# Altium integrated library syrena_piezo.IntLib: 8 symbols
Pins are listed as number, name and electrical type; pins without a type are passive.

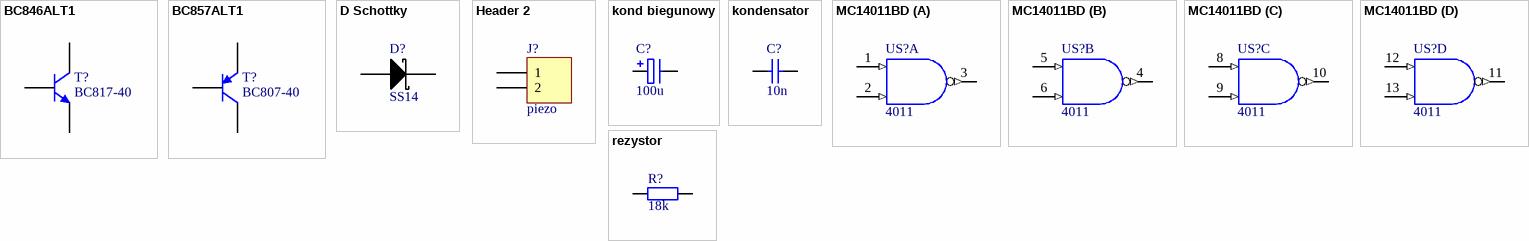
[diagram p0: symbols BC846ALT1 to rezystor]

## BC846ALT1
designator T?, comment BC817-40
General Purpose Transistor NPN Silicon
footprint 318-08 (SOT-23; 3 Leads; Body 3.0 x 2.6 mm, inc. leads (LxW max))
simulation model BC846ALT1 (NPN)
signal-integrity model BC846ALT1
pins: 1 B, 2 E, 3 C

## BC857ALT1
designator T?, comment BC807-40
General Purpose Transistor PNP Silicon
footprint 318-08 (SOT-23; 3 Leads; Body 3.0 x 2.6 mm, inc. leads (LxW max))
simulation model BC857ALT1 (PNP)
signal-integrity model BC857ALT1
pins: 1 B, 2 E, 3 C

## D Schottky
designator D?, comment SS14
Schottky Diode
footprint dioda 10mm
footprint dioda 17,5mm
footprint SMC/DO-214AB
footprint SMA/DO-214AC
pins: 1 A, 2 K

## Header 2
designator J?, comment piezo
Header, 2-Pin
footprint HDR1X2 (Connector; Header; 2 Position)
signal-integrity model Connector
pins: 1, 2

## kond biegunowy
designator C?, comment 100u
Polarized Capacitor
footprint Tantal B 3528-1411 (Capacitor, SM Tantalum; Body 3.5 x 2.8 mm (LxW typ))
footprint Tantal C 6032-2412 (Capacitor, SM Tantalum; Body 6.0 x 3.2 mm (LxW typ))
footprint Tantal D 7343-2917 (Capacitor, SM Tantalum; Body 7.3 x 4.3 mm (LxW typ))
footprint 2,5/5mm elektrolit
footprint 3,5/7mm elektrolit
footprint 5/10mm elektrolit
footprint 2,5/7mm elektrolit
footprint 7,5/16mm elektrolit
footprint 5/12,5mm elektrolit
footprint Tantal A 3216-1206 (Capacitor, SM Tantalum; Body 3.2 x 1.6 mm (LxW typ))
footprint A SMD elektrolit
footprint B SMD elektrolit
footprint C SMD elektrolit
footprint D SMD elektrolit
footprint E SMD elektrolit
footprint F SMD elektrolit
footprint 2,5/7mm le抗cy elektrolit
footprint 5/10mm le抗cy elektrolit
pins: 1, 2
1 alternate drawing of the same symbol

## kondensator
designator C?, comment 10n
footprint kond 2,5mm
footprint kond 7,5mm
footprint kond 10mm
footprint MELF-0805 (Metal Electrode Face (MELF) Resistor; Body 2 x 1.4 mm (LxDia))
footprint MELF-1206 (Metal Electrode Face (MELF) Resistor; Body 3.2 x 1.8 mm (LxDia))
footprint kond 15mm
footprint kond 5mm chudy
footprint kond 5mm gruby
footprint kond 5mm sredni
pins: 1, 2

## MC14011BD
designator US?, comment 4011
Quad 2-Input NAND Gate
footprint 751A-03_N (SOIC, 14-Leads, Body 8.7x3.9mm, Pitch 1.27mm, IPC Medium Density)
footprint 751A-03_L (SOIC, 14-Leads, Body 8.7x3.9mm, Pitch 1.27mm, IPC High Density)
footprint 751A-03_M (SOIC, 14-Leads, Body 8.7x3.9mm, Pitch 1.27mm, IPC Low Density)
pins on every part: 7 GND (power) hidden to GND, 14 VDD (power) hidden to VDD
part A pins: 1 A (in), 2 B (in), 3 ~{Y} (out)
part B pins: 4 ~{Y} (out), 5 A (in), 6 B (in)
part C pins: 8 A (in), 9 B (in), 10 ~{Y} (out)
part D pins: 11 ~{Y} (out), 12 A (in), 13 B (in)

## rezystor
designator R?, comment 18k
footprint rez 7,5mm
footprint rez 10mm
footprint rez 12,5mm
footprint rez 15mm
footprint rez 17,5mm
footprint MELF-0805 (Metal Electrode Face (MELF) Resistor; Body 2 x 1.4 mm (LxDia))
footprint MELF-1206 (Metal Electrode Face (MELF) Resistor; Body 3.2 x 1.8 mm (LxDia))
footprint rez_bocznik 20mm
footprint rez_5W kostka
pins: 1, 2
